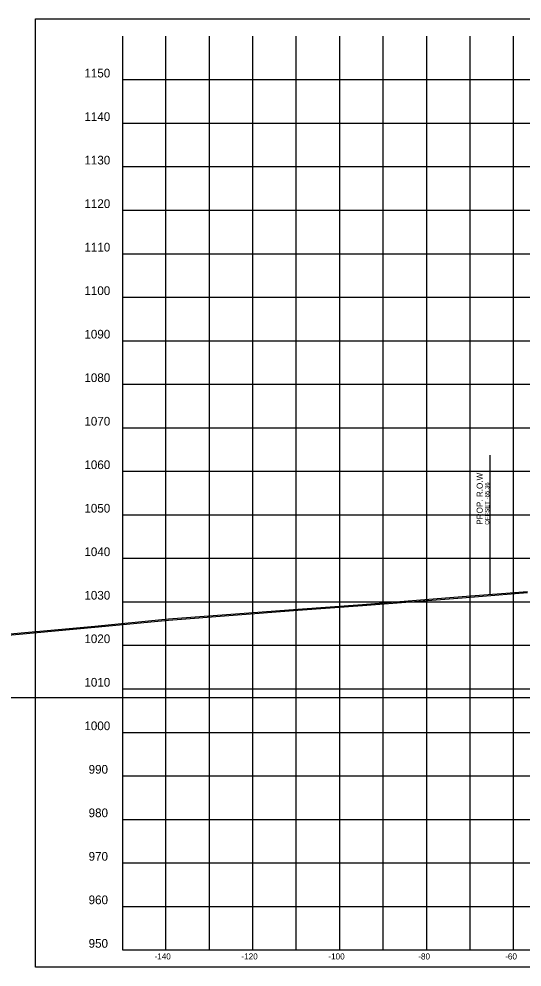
# Model space of a CAD drawing. Extents: x 5868 to 6683, y 2883 to 19120.
# Drawn here: x 6020 to 6135.7, y 8883.1 to 9101 of the extents above; entities that cross this region are included whole.
import ezdxf

# ---------------------------------------------------------------- set-up
doc = ezdxf.new("R2010")
doc.units = 0
for name, color, linetype in [('DESIGN - ROW - Right-of-Way and Easement Labels', 7, 'Continuous'), ('DESIGN - ROW - Right-of-Way Linework', 7, 'Continuous'), ('DESIGN - SHEET - Corner Text', 7, 'Continuous'), ('DESIGN - SHEET - Light Grid', 7, 'Continuous'), ('DESIGN - SHEET - Linework', 7, 'Continuous'), ('DESIGN - SHEET - Plot Shape', 7, 'Continuous'), ('SURVEY - GROUND - Bottom of Topsoil Layer', 7, 'Continuous'), ('SURVEY - GROUND - Top of Ground', 7, 'Continuous')]:
    doc.layers.add(name, color=color, linetype=linetype)

msp = doc.modelspace()

# ---------------------------------------------------------------- linework, layer by layer
at = {"layer": 'DESIGN - ROW - Right-of-Way Linework'}
msp.add_line((6128.42, 8968.77), (6128.42, 9000.77), dxfattribs=at)
at = {"layer": 'DESIGN - SHEET - Light Grid'}
msp.add_line((5893.78, 8945.07), (6193.78, 8945.07), dxfattribs=at)
at = {"layer": 'DESIGN - SHEET - Linework'}
for p, q in [((6053.78, 8887.07), (6053.78, 9097.07)), ((6063.78, 8887.07), (6063.78, 9097.07)), ((6073.78, 8887.07), (6073.78, 9097.07)), ((6083.78, 8887.07), (6083.78, 9097.07)), ((6093.78, 8887.07), (6093.78, 9097.07)), ((6103.78, 8887.07), (6103.78, 9097.07)), ((6113.78, 8887.07), (6113.78, 9097.07)), ((6123.78, 8887.07), (6123.78, 9097.07)), ((6133.78, 8887.07), (6133.78, 9097.07)), ((6043.78, 9087.07), (6343.78, 9087.07)), ((6043.78, 9077.07), (6343.78, 9077.07)), ((6043.78, 9067.07), (6343.78, 9067.07)), ((6043.78, 9057.07), (6343.78, 9057.07)), ((6043.78, 9047.07), (6343.78, 9047.07)), ((6043.78, 9037.07), (6343.78, 9037.07)), ((6043.78, 9027.07), (6343.78, 9027.07)), ((6043.78, 9017.07), (6343.78, 9017.07)), ((6043.78, 9007.07), (6343.78, 9007.07)), ((6043.78, 8997.07), (6343.78, 8997.07)), ((6043.78, 8987.07), (6343.78, 8987.07)), ((6043.78, 8977.07), (6343.78, 8977.07)), ((6043.78, 8967.07), (6343.78, 8967.07)), ((6043.78, 8957.07), (6343.78, 8957.07)), ((6043.78, 8947.07), (6343.78, 8947.07)), ((6043.78, 8937.07), (6343.78, 8937.07)), ((6043.78, 8927.07), (6343.78, 8927.07)), ((6043.78, 8917.07), (6343.78, 8917.07)), ((6043.78, 8907.07), (6343.78, 8907.07)), ((6043.78, 8897.07), (6343.78, 8897.07))]:
    msp.add_line(p, q, dxfattribs=at)
msp.add_lwpolyline([(6043.78, 9097.07), (6043.78, 8887.07), (6343.78, 8887.07), (6343.78, 9097.07)], dxfattribs=at)
at = {"layer": 'DESIGN - SHEET - Plot Shape'}
msp.add_lwpolyline([(6023.78, 9101.01), (6363.78, 9101.01), (6363.78, 8883.13), (6023.78, 8883.13)], close=True, dxfattribs=at)
at = {"layer": 'SURVEY - GROUND - Bottom of Topsoil Layer'}
for p, q in [((6099, 8966.21), (6121.93, 8968)), ((6121.93, 8968), (6136.97, 8969.22)), ((6084.14, 8965.13), (6099, 8966.21)), ((6054.38, 8962.88), (6084.14, 8965.13)), ((6037.47, 8961.22), (6054.38, 8962.88)), ((6009.47, 8958.69), (6037.47, 8961.22))]:
    msp.add_line(p, q, dxfattribs=at)
at = {"layer": 'SURVEY - GROUND - Top of Ground'}
msp.add_lwpolyline([(6009.47, 8958.94), (6037.47, 8961.47), (6054.38, 8963.13), (6084.14, 8965.38), (6099, 8966.46), (6121.93, 8968.25), (6136.97, 8969.47)], dxfattribs=at)

# ---------------------------------------------------------------- texts
at = {"layer": 'DESIGN - ROW - Right-of-Way and Easement Labels'}
for s, height, p in [('PROP. R.O.W.', 1.4, (6126.67, 8984.77)), ('OFFSET -65.36', 1, (6128.17, 8984.77))]:
    msp.add_text(s, height=height, rotation=90, dxfattribs=at).set_placement(p)
at = {"layer": 'DESIGN - SHEET - Corner Text'}
for s, height, p in [('1150', 2, (6035.03, 9087.57)), ('1140', 2, (6035.03, 9077.57)), ('1130', 2, (6035.03, 9067.57)), ('1120', 2, (6035.03, 9057.57)), ('1110', 2, (6035.03, 9047.57)), ('1100', 2, (6035.03, 9037.57)), ('1090', 2, (6035.03, 9027.57)), ('1080', 2, (6035.03, 9017.57)), ('1070', 2, (6035.03, 9007.57)), ('1060', 2, (6035.03, 8997.57)), ('1050', 2, (6035.03, 8987.57)), ('1040', 2, (6035.03, 8977.57)), ('1030', 2, (6035.03, 8967.57)), ('1020', 2, (6035.03, 8957.57)), ('1010', 2, (6035.03, 8947.57)), ('1000', 2, (6035.03, 8937.57)), ('990', 2, (6036, 8927.57)), ('980', 2, (6036, 8917.57)), ('970', 2, (6036, 8907.57)), ('960', 2, (6036, 8897.57)), ('950', 2, (6036, 8887.57)), ('-140', 1.4, (6051.16, 8884.87)), ('-120', 1.4, (6071.16, 8884.87)), ('-100', 1.4, (6091.16, 8884.87)), ('-80', 1.4, (6111.84, 8884.87)), ('-60', 1.4, (6131.84, 8884.87))]:
    msp.add_text(s, height=height, dxfattribs=at).set_placement(p)

doc.saveas('drawing.dxf')
